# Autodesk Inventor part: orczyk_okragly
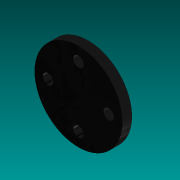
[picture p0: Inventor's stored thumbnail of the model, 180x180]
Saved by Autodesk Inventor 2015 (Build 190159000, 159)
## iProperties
Created: 2016-02
Part Number: orczyk_okragly
Material: Generic
Document SubType Name: Modeling
Designer: Rafał
Density: 1 g/cm^3
Appearance: Glossy - Black
Author: Rafał
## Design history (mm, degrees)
sketch "Sketch1"
  geometry: C1 r 10.5 at (0, 0); 1 further point
  constraints: 1 centre point, 1 coincident
  dimensions: "d0" = 21 diameter of C1
extrude "Extrusion1" new body sketch "Sketch1" distance "d1" = 2.3; taper "d2" = 0 deg
sketch "Sketch2"
  geometry: C1 r 4.5 at (0, 0); 1 further point
  constraints: 1 centre point, 1 coincident
  dimensions: "d3" = 9 diameter of C1
extrude "Extrusion2" join sketch "Sketch2" distance "d4" = 3.2; taper "d5" = 0 deg
sketch "Sketch3"
  geometry: C1 r 3 at (0, 0); 1 further point
  constraints: 1 centre point, 1 coincident
  dimensions: "d6" = 6 diameter of C1
extrude "Extrusion3" cut sketch "Sketch3" distance "d7" = 3; taper "d8" = 0 deg
sketch "Sketch4"
  geometry: C1 r 1.25 at (0, -7.25); C2 r 1.25 at (0, 7.25); C3 r 1.25 at (-7.25, 0); C4 r 1.25 at (7.25, 0); A1 r 7.25 centre (0, 0) between (0, -7.25) and (0, 7.25); 1 further point
  constraints: 5 centre point, 4 point on circle, 1 coincident
  dimensions: "d9" = 14.5 diameter of A1; "d10" = 2.5 diameter of C1; "d11" = 2.5 diameter of C2; "d12" = 2.5 diameter of C3; "d13" = 2.5 diameter of C4
extrude "Extrusion4" cut sketch "Sketch4" distance "d14" = 3; taper "d15" = 0 deg
body "Solid1"
